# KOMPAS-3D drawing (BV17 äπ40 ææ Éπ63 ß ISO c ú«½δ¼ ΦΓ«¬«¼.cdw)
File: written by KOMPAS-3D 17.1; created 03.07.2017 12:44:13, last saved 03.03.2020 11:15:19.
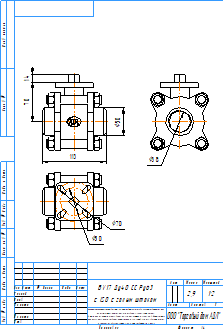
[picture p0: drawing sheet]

Sheet 1: A4, portrait

Title block, sheet 1: name: BV17 Ду40 СС Ру63 / с ISO c голым штоком; material: Сталь 20  ГОСТ 1050-88; mass: 2,9; sheets: 1; sheet format: A4; stored path: C:\Users\kka\KOMPAS_Work\!Trash\СС02 СС03 ФФ Смотровые стекла\СС01.cdw

Views: Спереди 4, Проекционный вид 5, Проекционный вид 6
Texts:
  Klimkovich
  ADL
  Рама для чертежей
  Лит-Масса-Масштаб
  Материал-Предприятие
  Масштаб
  Изм.
  Лист
  № докум.
  Подп.
  Дата
  Лит.
  Разраб.
  Пров.
  Т.контр.
  Листов
  Внимание! Данный продукт является объектом авторского права ООО «Торговый Дом АДЛ».
  Запрещается изменение, копирование, распространение
  (в том числе путем копирования на другие сайты и ресурсы в Интернете)
  или любое иное использование информации и объектов без предварительного
  согласия правообладателя (ООО «Торговый Дом АДЛ»).
  Н.контр.
  Утв.
  ООО "Торговый дом АДЛ"
  Изменение
  Номер документа
  Подпись
  Обозначение документа
  Наименование изделия
  Масса изделия по ГОСТ 2.109-73
  Порядковый номер листа
  Общее количество листов в документе
  Характер работы, выполненной лицом, подписавшим документ
  Наименование или индекс предприятия, выпускающего документ
  Инв. № подл.
  Подп. и дата
  Взам. инв. №
  Инв. № дубл.
  Инвентарный номер подлинника по ГОСТ 2.501-68
  Подпись принявшего подлинник в отдел технической документации
  Инвентарный номер подлинника, взамен которого выпущен данный подлинник
  Инвентарный номер дубликата по ГОСТ 2.502-68
  Подпись принявшего дубликат в отдел технической документации
  Справ. №
  Перв. примен.
  Обозначение документа, взамен или на основании которого выпущен данный документ
  Обозначение документа, в котором впервые записан данный документ
  Подпись лица, копировавшего чертеж
  Обозначение формата листа
  !Рама для чертежа
Dimensions and other numbers on the sheet: 113; 70; 50; 14; 38; 1:2; 1; 2,9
